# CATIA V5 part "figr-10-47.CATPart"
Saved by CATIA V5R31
Part number: Part1
Bounding box of the stored display mesh (mm): x 0 to 149.165, y -56.328 to 246, z -79.956 to 99.365
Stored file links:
  D:\PROJECTS\Project 2021\US EDITION\CATIA V5 6R 2021\Resources\Part Files\c10_catia_v5_6r2021_prt\c10_catia_v5_6r2021_prt\figr-10-47.CATPart
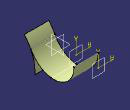
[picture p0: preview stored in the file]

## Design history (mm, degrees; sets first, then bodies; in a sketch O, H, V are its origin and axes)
Body1 (main body)
  Sketch1 on yz-plane, origin (0, 0, 0), H (0, 1, 0), V (0, 0, 1)
    arc A1 centre (-231.2925, -65.467) radius 240.3792 from (-56.3278, 99.3648) to (8.6496, -79.9559) cw
    coincidence: A1 O
  Extrude1: Element1 Sketch1, Lim1 149, Lim2 0
  Sketch2 on zx-plane, origin (0, 0, 0), H (-1, 0, 0), V (0, 0, 1)
    line L1 (-147.95, 52.1519) -> (0, 52.1519)
    point P1 (0, 52.1519)
    coincidence: P1 V
    horizontal: L1 H
  Project1: ToProject Sketch2, Support Extrude1
  Plane1: type Offset, RefPlane zx-plane, Offset 110
  Plane2: type Offset, RefPlane Plane1, Offset 136
  Sketch3 on Plane1, origin (0, 110, 0), H (-1, 0, 0), V (0, 0, 1)
    line L1 (-149.1647, -46.834) -> (0, -46.834)
    point P1 (0, -46.834)
    coincidence: P1 V
    horizontal: L1 H
  Sketch4 on Plane2, origin (0, 246, 0), H (-1, 0, 0), V (0, 0, 1)
    line L1 (-148.4227, 79.0713) -> (0, 79.0713)
    point P1 (0, 79.0713)
    coincidence: P1 V
    horizontal: L1 H
  Sweep1: type Conic, Guide ({sweepconicextendedguide Guide Project1, Reference Extrude1, Angle 0}; Sketch3; {sweepconicextendedguide Guide Sketch4, Reference Plane2, Angle 0})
